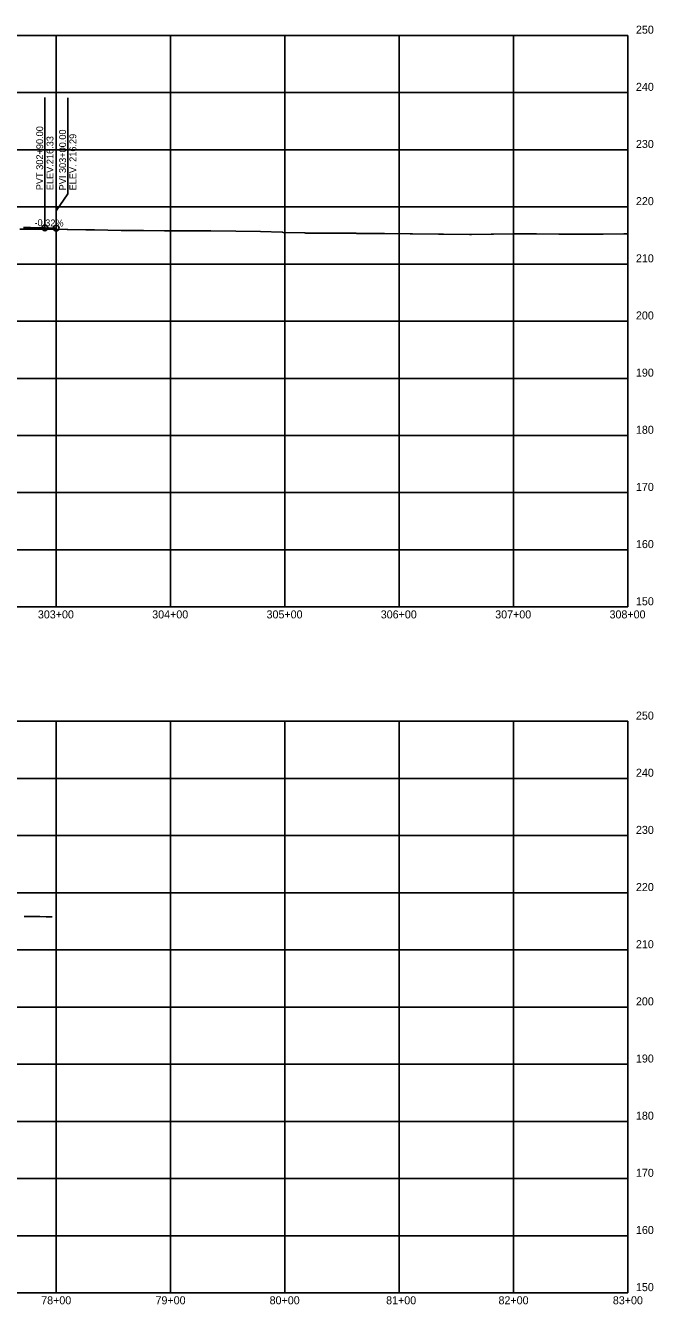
# Model space of a CAD drawing. Extents: x 1138442 to 1165793, y 1654070 to 1657687.
# Drawn here: x 1164527 to 1165076, y 1654070 to 1655189 of the extents above; entities that cross this region are included whole.
import ezdxf

# ---------------------------------------------------------------- set-up
doc = ezdxf.new("R2010")
doc.units = 0
for name, color, linetype in [('B_Dimensions', 7, 'Continuous'), ('R_Axis', 7, 'Continuous'), ('R_Axis Annot', 7, 'Continuous'), ('R_Grid', 7, 'Continuous'), ('R_Proposed Const Limits_Hand', 7, 'Continuous'), ('R_Vert Alg Annot', 7, 'Continuous')]:
    doc.layers.add(name, color=color, linetype=linetype)

msp = doc.modelspace()

# ---------------------------------------------------------------- linework, layer by layer
at = {"layer": 'B_Dimensions'}
msp.add_line((1164543.6, 1655012), (1164553.6, 1655011.8), dxfattribs=at)
msp.add_lwpolyline([(1164524.9, 1655012.4), (1164527, 1655012.4), (1164529, 1655012.3), (1164531.1, 1655012.3), (1164533.2, 1655012.2), (1164535.3, 1655012.2), (1164537.4, 1655012.2), (1164539.5, 1655012.1), (1164541.5, 1655012.1), (1164543.6, 1655012)], dxfattribs=at)
at = {"layer": 'R_Axis'}
for p, q in [((1165053.6, 1654680.4), (1165053.6, 1655180.4)), ((1163553.6, 1654680.4), (1165053.6, 1654680.4)), ((1165053.6, 1654080.4), (1165053.6, 1654580.4)), ((1163553.6, 1654080.4), (1165053.6, 1654080.4))]:
    msp.add_line(p, q, dxfattribs=at)
at = {"layer": 'R_Grid'}
for p, q in [((1163553.6, 1655180.4), (1165053.6, 1655180.4)), ((1163553.6, 1655180.4), (1165053.6, 1655180.4)), ((1164553.6, 1654680.4), (1164553.6, 1655180.4)), ((1164653.6, 1654680.4), (1164653.6, 1655180.4)), ((1164753.6, 1654680.4), (1164753.6, 1655180.4)), ((1164853.6, 1654680.4), (1164853.6, 1655180.4)), ((1164953.6, 1654680.4), (1164953.6, 1655180.4)), ((1163553.6, 1655130.4), (1165053.6, 1655130.4)), ((1163553.6, 1655080.4), (1165053.6, 1655080.4)), ((1163553.6, 1655030.4), (1165053.6, 1655030.4)), ((1163553.6, 1654980.4), (1165053.6, 1654980.4)), ((1163553.6, 1654930.4), (1165053.6, 1654930.4)), ((1163553.6, 1654880.4), (1165053.6, 1654880.4)), ((1163553.6, 1654830.4), (1165053.6, 1654830.4)), ((1163553.6, 1654780.4), (1165053.6, 1654780.4)), ((1163553.6, 1654730.4), (1165053.6, 1654730.4)), ((1163553.6, 1654580.4), (1165053.6, 1654580.4)), ((1163553.6, 1654580.4), (1165053.6, 1654580.4)), ((1164553.6, 1654080.4), (1164553.6, 1654580.4)), ((1164653.6, 1654080.4), (1164653.6, 1654580.4)), ((1164753.6, 1654080.4), (1164753.6, 1654580.4)), ((1164853.6, 1654080.4), (1164853.6, 1654580.4)), ((1164953.6, 1654080.4), (1164953.6, 1654580.4)), ((1163553.6, 1654530.4), (1165053.6, 1654530.4)), ((1163553.6, 1654480.4), (1165053.6, 1654480.4)), ((1163553.6, 1654430.4), (1165053.6, 1654430.4)), ((1163553.6, 1654380.4), (1165053.6, 1654380.4)), ((1163553.6, 1654330.4), (1165053.6, 1654330.4)), ((1163553.6, 1654280.4), (1165053.6, 1654280.4)), ((1163553.6, 1654230.4), (1165053.6, 1654230.4)), ((1163553.6, 1654180.4), (1165053.6, 1654180.4)), ((1163553.6, 1654130.4), (1165053.6, 1654130.4))]:
    msp.add_line(p, q, dxfattribs=at)
at = {"layer": 'R_Proposed Const Limits_Hand'}
for points in [[(1164521.8, 1655011), (1164542.3, 1655010.8), (1164542.6, 1655010.8), (1164563.2, 1655010.6), (1164563.4, 1655010.6), (1164563.6, 1655010.6), (1164579.5, 1655010.3), (1164587, 1655010.2), (1164587.1, 1655010.2), (1164610.4, 1655009.8), (1164610.8, 1655009.8), (1164629.4, 1655009.7), (1164630, 1655009.7), (1164648.3, 1655009.5), (1164649.3, 1655009.5), (1164668.5, 1655009.4), (1164669, 1655009.4), (1164681.5, 1655009.4), (1164688.6, 1655009.3), (1164688.9, 1655009.3), (1164710.5, 1655009), (1164732.2, 1655008.8), (1164732.3, 1655008.8), (1164751.3, 1655008.2), (1164751.7, 1655008.2), (1164752.1, 1655008.1), (1164771.1, 1655007.6), (1164772, 1655007.5), (1164793.7, 1655007.4), (1164815.8, 1655007.3), (1164816.3, 1655007.2), (1164839.4, 1655007), (1164840.8, 1655007), (1164863, 1655006.8), (1164865.3, 1655006.8), (1164888, 1655006.5), (1164890.2, 1655006.5), (1164892.4, 1655006.5), (1164915.1, 1655006.2), (1164916.7, 1655006.2), (1164934.1, 1655006.5), (1164935.9, 1655006.5), (1164953.1, 1655006.8), (1164955.3, 1655006.8), (1164973.7, 1655006.7), (1164993.1, 1655006.6), (1164994.2, 1655006.6), (1165011.8, 1655006.6), (1165012.7, 1655006.6), (1165013.5, 1655006.6), (1165031.1, 1655006.6), (1165031.8, 1655006.6), (1165050, 1655006.7), (1165053.6, 1655006.8)], [(1164525.6, 1654409.5), (1164528.6, 1654409.5), (1164533.9, 1654409.5), (1164539.3, 1654409.5), (1164544.7, 1654409.4), (1164544.9, 1654409.4), (1164545.3, 1654409.4), (1164550.1, 1654409.4)]]:
    msp.add_lwpolyline(points, dxfattribs=at)
at = {"layer": 'R_Vert Alg Annot'}
for p, q in [((1164543.6, 1655042), (1164543.6, 1655126)), ((1164563.6, 1655041.8), (1164563.6, 1655125.8)), ((1164543.6, 1655012), (1164543.6, 1655042))]:
    msp.add_line(p, q, dxfattribs=at)
msp.add_lwpolyline([(1164553.6, 1655020.8), (1164553.6, 1655026.8), (1164563.6, 1655041.8)], dxfattribs=at)
for centre in [(1164543.6, 1655012), (1164553.6, 1655011.8)]:
    msp.add_circle(centre, 2.5, dxfattribs=at)

# ---------------------------------------------------------------- texts
at = {"layer": 'R_Axis Annot'}
for s, p in [('250', (1165060.6, 1655181.9)), ('250', (1165060.6, 1655181.9)), ('240', (1165060.6, 1655131.9)), ('230', (1165060.6, 1655081.9)), ('220', (1165060.6, 1655031.9)), ('210', (1165060.6, 1654981.9)), ('200', (1165060.6, 1654931.9)), ('190', (1165060.6, 1654881.9)), ('180', (1165060.6, 1654831.9)), ('170', (1165060.6, 1654781.9)), ('160', (1165060.6, 1654731.9)), ('150', (1165060.6, 1654681.9)), ('303+00', (1164537.5, 1654670.4)), ('304+00', (1164637.5, 1654670.4)), ('305+00', (1164737.5, 1654670.4)), ('306+00', (1164837.4, 1654670.4)), ('307+00', (1164937.5, 1654670.4)), ('308+00', (1165037.5, 1654670.4)), ('250', (1165060.6, 1654581.9)), ('250', (1165060.6, 1654581.9)), ('240', (1165060.6, 1654531.9)), ('230', (1165060.6, 1654481.9)), ('220', (1165060.6, 1654431.9)), ('210', (1165060.6, 1654381.9)), ('200', (1165060.6, 1654331.9)), ('190', (1165060.6, 1654281.9)), ('180', (1165060.6, 1654231.9)), ('170', (1165060.6, 1654181.9)), ('160', (1165060.6, 1654131.9)), ('150', (1165060.6, 1654081.9)), ('78+00', (1164540.4, 1654070.4)), ('79+00', (1164640.4, 1654070.4)), ('80+00', (1164740.2, 1654070.4)), ('81+00', (1164842.1, 1654070.4)), ('82+00', (1164940.4, 1654070.4)), ('83+00', (1165040.4, 1654070.4))]:
    msp.add_text(s, height=7, dxfattribs=at).set_placement(p)
at = {"layer": 'R_Vert Alg Annot'}
for s, rotation, p in [('PVT 302+90.00', 90, (1164542.1, 1655045)), ('ELEV.216.33', 90, (1164551.1, 1655045)), ('PVI 303+00.00', 90, (1164562.1, 1655044.8)), ('ELEV. 216.29', 90, (1164571.1, 1655044.8)), ('-0.32%', 359.0833, (1164534.5, 1655013.6))]:
    msp.add_text(s, height=6, rotation=rotation, dxfattribs=at).set_placement(p)

doc.saveas('drawing.dxf')
